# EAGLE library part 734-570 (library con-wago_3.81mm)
Serie 734, Federleiste mit abgewinkelten Einlötstiften / Series 734, Female connector with angled solder pins Polzahl / Pole No.: 10 Bemessungsspannung / Rated Voltage: 160 V Nennstrom / Nominal Current: 10 A Lötstiftlänge: / Solder Pin Length: 3.8 mm Farbe / Color: orange / orange Stand: 01.01.2012. Die jeweils aktuellen Daten zu diesem Artikel finden Sie in unserem Produktkatalog, den Sie unter www.wago.com einsehen können. As of: 01/01/2012. Please find the newest data for this article in our product catalogue, which can be viewed under www.wago.com.
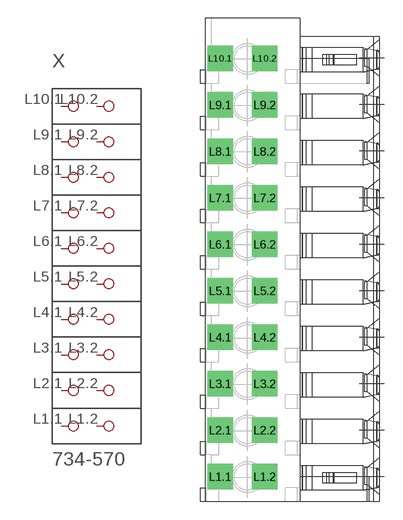
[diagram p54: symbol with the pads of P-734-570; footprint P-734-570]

Designator prefix X

## 734-570  [P-734-570]
L1.1  P1.1
L1.2  P1.2
L2.1  P2.1
L2.2  P2.2
L3.1  P3.1
L3.2  P3.2
L4.1  P4.1
L4.2  P4.2
L5.1  P5.1
L5.2  P5.2
L6.1  P6.1
L6.2  P6.2
L7.1  P7.1
L7.2  P7.2
L8.1  P8.1
L8.2  P8.2
L9.1  P9.1
L9.2  P9.2
L10.1  P10.1
L10.2  P10.2

## Footprint P-734-570 (pad centres in mm)
drill 1.4 square: L1.1 -5.943,-17.79; L1.2 -2.293,-17.79; L2.1 -5.943,-13.98; L2.2 -2.293,-13.98; L3.1 -5.943,-10.17; L3.2 -2.293,-10.17; L4.1 -5.943,-6.36; L4.2 -2.293,-6.36; L5.1 -5.943,-2.55; L5.2 -2.293,-2.55; L6.1 -5.943,1.26; L6.2 -2.293,1.26; L7.1 -5.943,5.07; L7.2 -2.293,5.07; L8.1 -5.943,8.88; L8.2 -2.293,8.88; L9.1 -5.943,12.69; L9.2 -2.293,12.69; L10.1 -5.943,16.5; L10.2 -2.293,16.5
